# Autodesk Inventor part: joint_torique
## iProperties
Shininess: 64.0
Length Units: 11269
Angle Units: 11279
Time Units: 11290
Mass Units: 11283
Length Display Precision: 3
Angle Display Precision: 2
Compacted: True
Part Number: joint_torique
Document SubType Name: Modeling
Created: 2004-05
Material: Par défaut
Designer: David
Density: 0.0
Volumn: 0.0
Area: 0.0
PropertySet Name: Model Information
Control State: 0
Master: False
Checked Out: False
Author: David
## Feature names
1. Révolution1 [Revolution]
